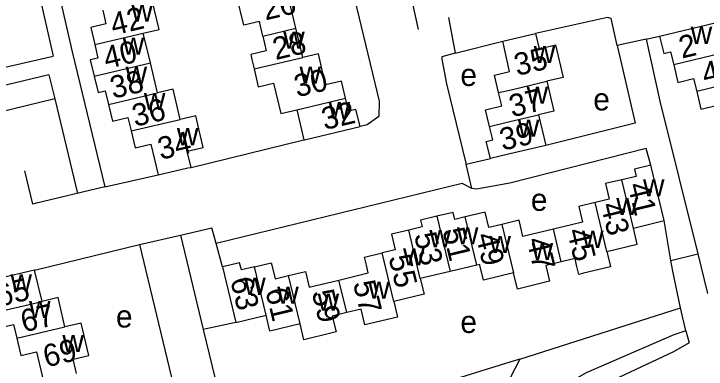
# Model space of a CAD drawing. Extents: x 157646 to 159241, y 379213 to 381217.
# Drawn here: x 159011 to 159135.3, y 380481.3 to 380545.1 of the extents above; entities that cross this region are included whole.
import ezdxf

# ---------------------------------------------------------------- set-up
doc = ezdxf.new("R2010")
doc.units = 0
for name, color, linetype in [('BLT_Basislijn', 7, 'Continuous'), ('BLT_Bebouwing', 7, 'Continuous'), ('BLT_Centroide', 7, 'Continuous'), ('BLT_Huisnummer', 7, 'Continuous'), ('BLT_Huisnummer_ tussenligend', 7, 'Continuous'), ('BLT_Onderverdeling_panden', 7, 'Continuous')]:
    doc.layers.add(name, color=color, linetype=linetype)

msp = doc.modelspace()

# ---------------------------------------------------------------- linework, layer by layer
at = {"layer": 'BLT_Basislijn'}
for p, q in [((159015.54, 380548.65), (159018.05, 380537.49)), ((159083.61, 380542.26), (159082.58, 380547.15)), ((159089.01, 380544.43), (159090.23, 380538.01)), ((159124.49, 380540.51), (159126.89, 380541.07)), ((159090.23, 380538.01), (159098.76, 380540.16)), ((159124.49, 380540.51), (159119.27, 380539.42)), ((159021.46, 380538.27), (159027.32, 380514.05)), ((159017.31, 380534.13), (158993.25, 380528.36)), ((159017.31, 380534.13), (159018.36, 380529.81)), ((159018.36, 380529.81), (158994.28, 380524.03)), ((159018.36, 380529.81), (159022.46, 380512.87)), ((159042.82, 380517.53), (159063.05, 380522.46)), ((159092.2, 380518.08), (159096.53, 380519.12)), ((159093.21, 380513.72), (159092.2, 380518.08)), ((159014.4, 380510.93), (159012.99, 380516.9)), ((159027.32, 380514.05), (159036.91, 380516.22)), ((159040.9, 380505.38), (159046.56, 380506.71)), ((159047.32, 380503.87), (159046.56, 380506.71)), ((159033.59, 380503.67), (159040.9, 380505.38)), ((159040.9, 380505.38), (159045.01, 380488.45)), ((159014.74, 380499.09), (159033.59, 380503.67)), ((159033.59, 380503.67), (159040.77, 380473.78)), ((159048.43, 380499.69), (159047.32, 380503.87)), ((159128.94, 380500.84), (159133.77, 380501.99)), ((159101.79, 380483.11), (159130.66, 380492.35)), ((159131.62, 380488.18), (159130.66, 380492.35)), ((159050.83, 380489.7), (159045.01, 380488.45))]:
    msp.add_line(p, q, dxfattribs=at)
for points in [[(159063.51, 380583.63), (159063.69, 380582.85), (159076.59, 380529.44), (159076.54, 380526.66), (159074.4, 380525.17), (159073.14, 380524.84)], [(159016.44, 380572.28), (159013.8, 380571.77), (159021.46, 380538.27)], [(159119.27, 380539.42), (159118.23, 380544.24), (159117.53, 380544.45), (159104.63, 380541.55)], [(159119.27, 380539.42), (159122.51, 380525.44), (159106.48, 380521.48)], [(159124.49, 380540.51), (159126.96, 380529.43), (159133.77, 380501.99)], [(158992.48, 380531.61), (159016.74, 380537.19), (159018.05, 380537.49)], [(159090.23, 380538.01), (159087.84, 380537.36), (159087.81, 380536.97), (159088.65, 380532.52), (159092.15, 380518.3), (159092.2, 380518.08)], [(159125.33, 380517.93), (159124.47, 380520.89), (159100, 380514.71), (159094.05, 380513.63), (159093.21, 380513.72)], [(159093.21, 380513.72), (159091.45, 380514.63), (159047.32, 380503.87)], [(159027.32, 380514.05), (159014.85, 380511.04), (159014.4, 380510.93)], [(159128.94, 380500.84), (159127.71, 380507.97)], [(159130.66, 380492.35), (159129.27, 380498.89), (159128.94, 380500.84)], [(159133.77, 380501.99), (159135.52, 380494.92)], [(159045.01, 380488.45), (159048.22, 380475.16), (159047.51, 380475.03)], [(159131.62, 380488.18), (159129.43, 380487.46), (159113.71, 380480.68), (159102.93, 380474.49), (159100, 380472.43), (159088.12, 380464.78), (159054.96, 380448.44)], [(159131.62, 380488.18), (159132.2, 380486.05), (159129.4, 380484.46), (159116.76, 380478.53), (159111.36, 380475.39), (159100, 380467.74), (159095.35, 380464.55), (159093.06, 380462.45), (159081.21, 380456.03), (159067.43, 380450.3), (159056.4, 380447.86), (159054.96, 380448.44)], [(159101.79, 380483.11), (159100, 380482.56), (159049.37, 380466.86)], [(159101.79, 380483.11), (159100, 380479.65), (159098.97, 380478.78), (159084.17, 380469.08), (159052.65, 380453.23)]]:
    msp.add_lwpolyline(points, dxfattribs=at)
at = {"layer": 'BLT_Bebouwing'}
for p, q in [((159126.89, 380541.07), (159136.85, 380543.44)), ((159062.87, 380537.25), (159061.64, 380542.49)), ((159035.51, 380536.26), (159034.25, 380541.61)), ((159036.77, 380530.9), (159035.51, 380536.26)), ((159061.77, 380527.88), (159063.05, 380522.46)), ((159105.18, 380526.97), (159106.48, 380521.48)), ((159127.71, 380507.97), (159125.33, 380517.93)), ((159122.21, 380506.65), (159127.71, 380507.97)), ((159048.43, 380499.69), (159050.83, 380489.7)), ((159094.09, 380500), (159089.31, 380498.85)), ((159014.74, 380499.09), (159004.81, 380496.74)), ((159016.07, 380493.49), (159014.74, 380499.09)), ((159089.31, 380498.85), (159083.96, 380497.57)), ((159050.83, 380489.7), (159056.27, 380491.01))]:
    msp.add_line(p, q, dxfattribs=at)
for points in [[(159061.64, 380542.49), (159060.37, 380547.85), (159063.14, 380548.5), (159062.45, 380551.47)], [(159055.68, 380541.08), (159055.07, 380543.7), (159052.28, 380543.04), (159050.93, 380548.75), (159053.74, 380549.41)], [(159034.25, 380541.61), (159037.09, 380542.28), (159035.79, 380547.79)], [(159026.96, 380545.71), (159027.54, 380543.26), (159024.81, 380542.61), (159025.53, 380539.56)], [(159055.68, 380541.08), (159056.3, 380538.47), (159053.52, 380537.81), (159053.74, 380536.87), (159054.13, 380535.19)], [(159098.76, 380540.16), (159100, 380540.46), (159104.63, 380541.55)], [(159104.63, 380541.55), (159105.28, 380538.8), (159108.22, 380539.5), (159109.6, 380533.68), (159106.64, 380532.99)], [(159126.89, 380541.07), (159127.63, 380537.97), (159128.88, 380538.27), (159129.43, 380535.95)], [(159025.53, 380539.56), (159026.1, 380537.13), (159024.74, 380536.81), (159025.43, 380533.88)], [(159098, 380530.94), (159097.26, 380534.1), (159099.99, 380534.75), (159098.76, 380540.16)], [(159070.52, 380529.95), (159069.8, 380533.02), (159066.97, 380532.35), (159065.66, 380537.91), (159062.87, 380537.25)], [(159129.43, 380535.95), (159130.18, 380532.79), (159133.01, 380533.46), (159133.56, 380531.15)], [(159054.13, 380535.19), (159054.89, 380532), (159057.62, 380532.64), (159058.9, 380527.21), (159061.77, 380527.88)], [(159025.43, 380533.88), (159026.12, 380530.96), (159027.42, 380531.27), (159027.99, 380528.83)], [(159106.64, 380532.99), (159107.91, 380527.62), (159105.18, 380526.97)], [(159040.86, 380526.13), (159039.58, 380531.56), (159036.77, 380530.9)], [(159096.38, 380524.89), (159095.67, 380527.88), (159098.57, 380528.56), (159098, 380530.94)], [(159133.56, 380531.15), (159134.31, 380527.98), (159137.14, 380528.65), (159138.36, 380523.53)], [(159073.14, 380524.84), (159072.41, 380527.92), (159071.07, 380527.6), (159070.52, 380529.95)], [(159027.99, 380528.83), (159028.71, 380525.8), (159031.5, 380526.46), (159032.07, 380524.06)], [(159042.82, 380517.53), (159042.13, 380520.43), (159045, 380521.11), (159043.85, 380525.98), (159043.66, 380526.79), (159040.86, 380526.13)], [(159063.05, 380522.46), (159063.16, 380522.48), (159073.14, 380524.84)], [(159096.53, 380519.12), (159095.8, 380522.2), (159096.95, 380522.47), (159096.38, 380524.89)], [(159032.07, 380524.06), (159032.79, 380521.01), (159035.62, 380521.68), (159036.91, 380516.22)], [(159106.48, 380521.48), (159100, 380519.94), (159096.53, 380519.12)], [(159036.91, 380516.22), (159042.21, 380517.47), (159042.82, 380517.53)], [(159125.33, 380517.93), (159122.37, 380517.22), (159122.68, 380515.92), (159120.13, 380515.31)], [(159120.13, 380515.31), (159117.18, 380514.61), (159117.85, 380511.82), (159115.35, 380511.22)], [(159115.35, 380511.22), (159112.4, 380510.51), (159113.07, 380507.71), (159107.86, 380506.46)], [(159098.6, 380507.3), (159096.25, 380506.74), (159095.59, 380509.5), (159092.02, 380508.65)], [(159086.94, 380508.76), (159084, 380508.05), (159084.29, 380506.86), (159081.87, 380506.28)], [(159092.02, 380508.65), (159090.18, 380508.2), (159089.87, 380509.46), (159086.94, 380508.76)], [(159107.86, 380506.46), (159102.38, 380505.15), (159101.69, 380508.05), (159100, 380507.64), (159098.6, 380507.3)], [(159081.87, 380506.28), (159078.76, 380505.54), (159079.43, 380502.74), (159077.09, 380502.18)], [(159117.45, 380502.46), (159122.9, 380503.77), (159122.21, 380506.65)], [(159069.36, 380497.32), (159074.63, 380498.58), (159074.3, 380500), (159073.96, 380501.43), (159077.09, 380502.18)], [(159117.45, 380502.46), (159118.03, 380500.01), (159118.11, 380499.7), (159113.25, 380498.54), (159112.4, 380498.34), (159112.01, 380500), (159111.73, 380501.18), (159109.26, 380500.59)], [(159054.18, 380499.7), (159051.84, 380499.13), (159051.63, 380500), (159051.53, 380500.43), (159049.77, 380500.01), (159048.43, 380499.69)], [(159054.18, 380499.7), (159055.43, 380500), (159057.22, 380500.43), (159057.33, 380500), (159057.9, 380497.55), (159060.3, 380498.13)], [(159100.69, 380498.58), (159095.28, 380497.28), (159094.65, 380500), (159094.62, 380500.13), (159094.09, 380500)], [(159109.26, 380500.59), (159106.8, 380500), (159106.49, 380499.92), (159107.16, 380497.09), (159101.38, 380495.7), (159100.69, 380498.58)], [(159060.3, 380498.13), (159063.36, 380498.86), (159064.04, 380496.04), (159069.36, 380497.32)], [(159083.96, 380497.57), (159084.63, 380494.76), (159079.18, 380493.45)], [(159020.19, 380488.91), (159018.94, 380494.17), (159016.07, 380493.49)], [(159079.18, 380493.45), (159079.85, 380490.64), (159074.03, 380489.25), (159073.35, 380492.09), (159070.76, 380491.47)], [(159007.45, 380491.45), (159008.11, 380488.67), (159010.95, 380489.34), (159011.54, 380486.86)], [(159062.38, 380489.44), (159056.95, 380488.14), (159056.27, 380491.01)], [(159070.76, 380491.47), (159068.16, 380490.85), (159068.85, 380488), (159067.92, 380487.77), (159063.06, 380486.61), (159062.38, 380489.44)], [(159022.25, 380480.53), (159021.64, 380483.12), (159024.49, 380483.8), (159023.12, 380489.6), (159020.19, 380488.91)], [(159011.54, 380486.86), (159012.26, 380483.8), (159015.06, 380484.46), (159016.33, 380479.12)]]:
    msp.add_lwpolyline(points, dxfattribs=at)
at = {"layer": 'BLT_Onderverdeling_panden'}
for p, q in [((159055.68, 380541.08), (159061.64, 380542.49)), ((159025.53, 380539.56), (159034.25, 380541.61)), ((159054.13, 380535.19), (159062.87, 380537.25)), ((159138.14, 380538.02), (159129.43, 380535.95)), ((159025.43, 380533.88), (159035.51, 380536.26)), ((159142.23, 380533.21), (159133.56, 380531.15)), ((159027.99, 380528.83), (159036.77, 380530.9)), ((159061.77, 380527.88), (159070.52, 380529.95)), ((159032.07, 380524.06), (159040.86, 380526.13)), ((159122.21, 380506.65), (159120.13, 380515.31)), ((159117.45, 380502.46), (159115.35, 380511.22)), ((159086.94, 380508.76), (159089.31, 380498.85)), ((159094.09, 380500), (159092.02, 380508.65)), ((159098.6, 380507.3), (159100.69, 380498.58)), ((159083.96, 380497.57), (159081.87, 380506.28)), ((159109.26, 380500.59), (159107.86, 380506.46)), ((159079.18, 380493.45), (159077.09, 380502.18)), ((159056.27, 380491.01), (159054.18, 380499.7)), ((159062.38, 380489.44), (159060.3, 380498.13)), ((159070.76, 380491.47), (159069.36, 380497.32)), ((159007.45, 380491.45), (159016.07, 380493.49)), ((159011.54, 380486.86), (159020.19, 380488.91))]:
    msp.add_line(p, q, dxfattribs=at)
for points in [[(159098, 380530.94), (159100, 380531.41), (159106.64, 380532.99)], [(159096.38, 380524.89), (159100, 380525.74), (159105.18, 380526.97)]]:
    msp.add_lwpolyline(points, dxfattribs=at)

# ---------------------------------------------------------------- texts
at = {"layer": 'BLT_Centroide'}
for s, p in [('w', (159032.1, 380543.69)), ('w', (159059.36, 380538.84)), ('w', (159132.48, 380539.69)), ('w', (159030.55, 380537.75)), ('w', (159104.32, 380536.25)), ('w', (159031.07, 380532.53)), ('w', (159062.28, 380532.56)), ('e', (159091.15, 380532.13)), ('w', (159103.04, 380528.94)), ('w', (159034.35, 380527.81)), ('e', (159115, 380527.75)), ('w', (159067.49, 380526.19)), ('w', (159101.46, 380523.03)), ('w', (159040.28, 380521.5)), ('w', (159123.92, 380512.33)), ('e', (159103.8, 380509.73)), ('w', (159119.12, 380508.97)), ('w', (159085.59, 380503.2)), ('w', (159090.52, 380503.72)), ('w', (159112.98, 380503.08)), ('w', (159096.36, 380502.16)), ('w', (159103.94, 380500.92)), ('w', (159080.86, 380499.94)), ('w', (159010.41, 380495.28)), ('w', (159052.34, 380494.66)), ('w', (159058.28, 380493.06)), ('w', (159074.61, 380493.97)), ('w', (159065.53, 380491.8)), ('w', (159013.74, 380490.5)), ('e', (159029.34, 380488.8)), ('e', (159091.15, 380487.82)), ('w', (159019.72, 380484.38))]:
    msp.add_text(s, height=4, dxfattribs=at).set_placement(p)
at = {"layer": 'BLT_Huisnummer'}
for s, rotation, p in [('42', 13.2666, (159028.88, 380541.18)), ('28', 13.2654, (159057.98, 380536.77)), ('2', 13.376, (159130.89, 380537.04)), ('35', 13.3094, (159101.32, 380533.92)), ('38', 13.2666, (159028.82, 380529.83)), ('32', 13.2654, (159066.77, 380524.21)), ('39', 13.3041, (159098.72, 380520.5)), ('34', 13.2666, (159037.36, 380518.86)), ('41', 283.4867, (159121.15, 380514.37)), ('53', 283.4867, (159082.82, 380505.41)), ('45', 283.4867, (159110.26, 380506.16)), ('49', 283.4867, (159093.87, 380505.35)), ('65', 13.343, (159008.35, 380492.5)), ('63', 283.4812, (159049.83, 380497.37)), ('57', 283.4867, (159071.86, 380496.78)), ('69', 13.3455, (159016.81, 380481.61))]:
    msp.add_text(s, height=4, rotation=rotation, dxfattribs=at).set_placement(p)
at = {"layer": 'BLT_Huisnummer_ tussenligend'}
for s, rotation, p in [('26', 13.2654, (159056.16, 380543.89)), ('40', 13.2666, (159027.63, 380535.16)), ('4', 13.376, (159135.02, 380532.29)), ('30', 13.2654, (159061.83, 380530.09)), ('37', 13.3094, (159100.42, 380526.5)), ('36', 13.2666, (159032.76, 380524.79)), ('43', 283.4867, (159116.31, 380510.8)), ('51', 283.4867, (159087.9, 380506.24)), ('47', 283.4867, (159102.99, 380504.54)), ('55', 283.4867, (159078.23, 380501.41)), ('61', 283.4867, (159056.12, 380495.44)), ('59', 283.4867, (159064.46, 380495.14)), ('67', 13.343, (159012.78, 380487.9))]:
    msp.add_text(s, height=4, rotation=rotation, dxfattribs=at).set_placement(p)

doc.saveas('drawing.dxf')
